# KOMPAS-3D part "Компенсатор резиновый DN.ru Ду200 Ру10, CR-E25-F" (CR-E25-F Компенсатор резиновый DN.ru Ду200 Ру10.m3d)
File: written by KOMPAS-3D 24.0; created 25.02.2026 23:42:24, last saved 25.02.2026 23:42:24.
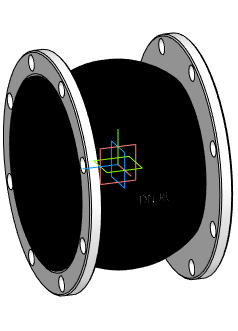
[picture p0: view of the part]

Document properties: Автор: DN.RU; Полное имя файла: D:\PROJECT CAD\DN.RU\...178(4)(ACTUALE). CR-E25-F Компенсатор резиновый DN.ru Ру10-16\DN200_PN10\CR-E25-F Компенсатор резиновый DN.ru Ду200 Ру10.m3d

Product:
- Body: Твердое тело2  | qty 1
    Масса: 43.88726
- Part/product: Компенсатор резиновый DN.ru Ду200 Ру10  | designation CR-E25-F
    Масса: 19.43
    Раздел спецификации: Прочие изделия
    Комментарий: D140-02168
    Примечание: D140-02168
    additional columns: Типовые

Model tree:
1. Твердое тело2  (labels: Твердое тело2)

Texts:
  CR-E25-F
